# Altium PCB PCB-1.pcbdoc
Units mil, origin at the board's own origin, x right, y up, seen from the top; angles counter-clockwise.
Board outline 1312.9 x 463.6 mil, 2 copper layers (Top Layer, Bottom Layer), stack 62.2 mil thick; 18 components, 12 nets, 66 pads, 14 vias.
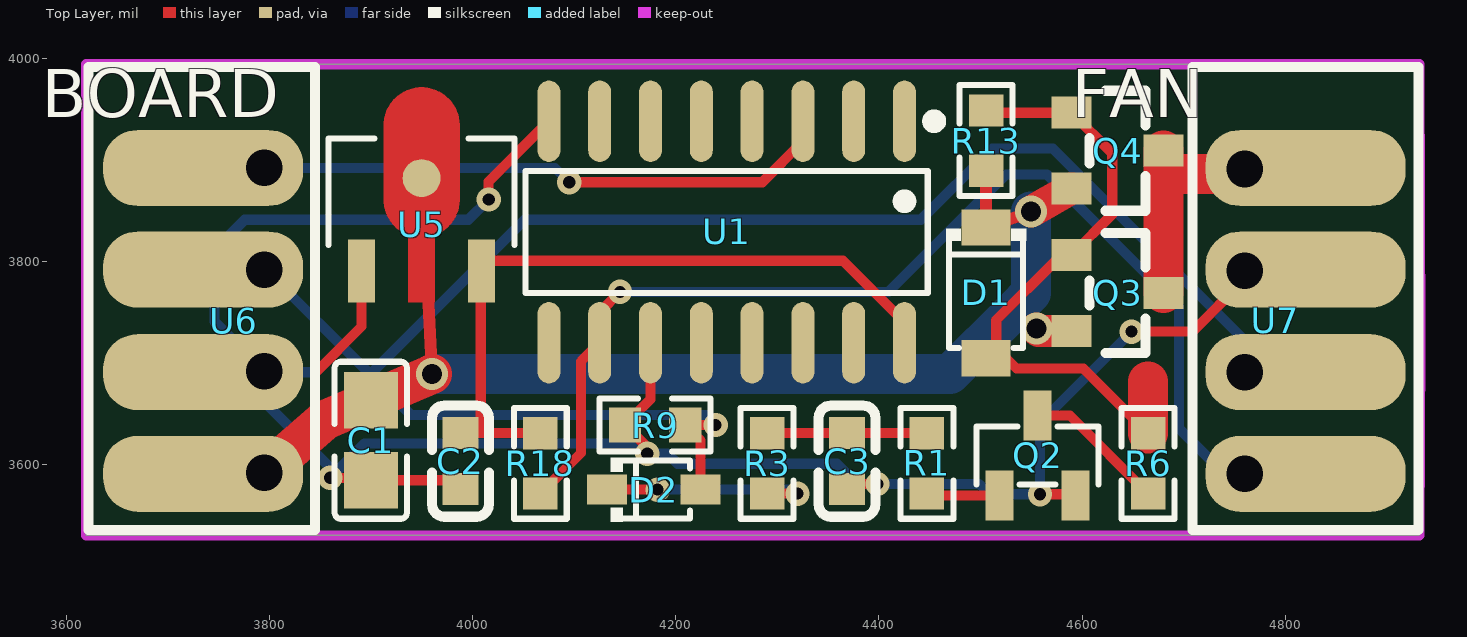
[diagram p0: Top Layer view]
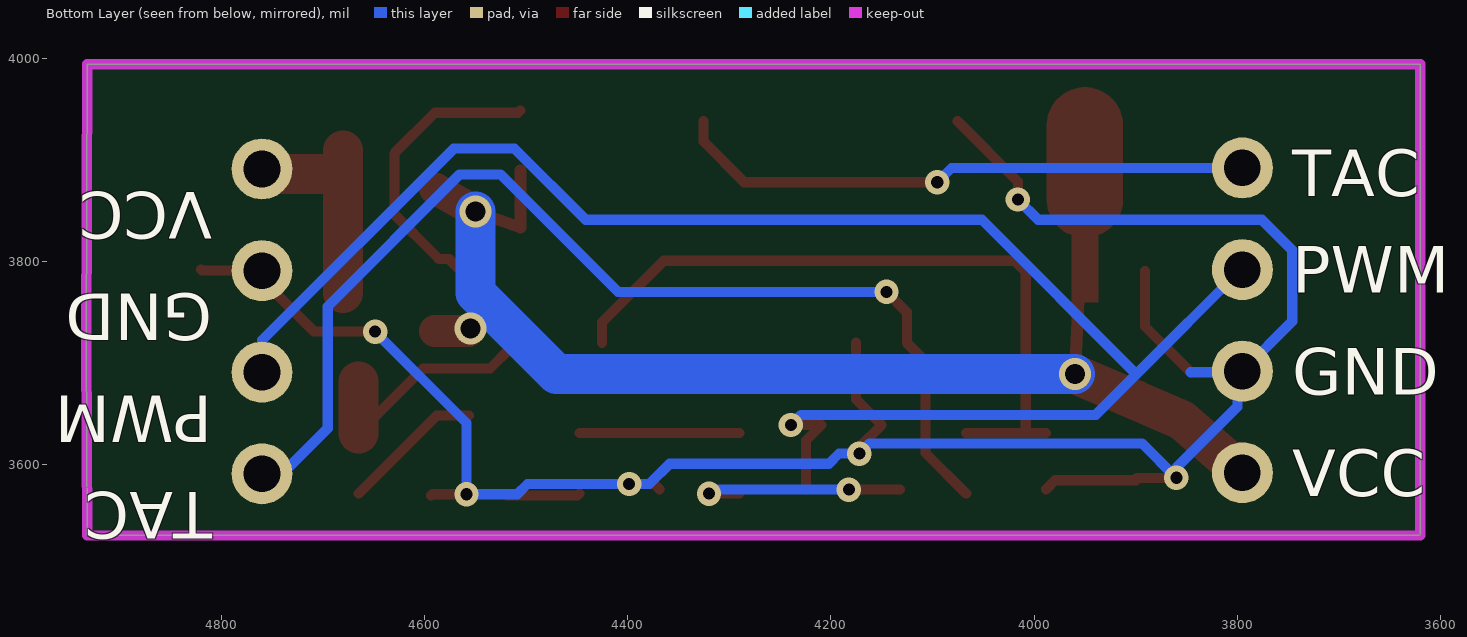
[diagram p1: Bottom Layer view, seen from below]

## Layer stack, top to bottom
Top Solder Mask Layer: solder mask 0.4, Dk 3.3
Top Layer: signal copper 1.4
Dielectric1: surface 59.4, FR4, Dk 4.5
Bottom Layer: signal copper 1.4
Bottom Solder Mask Layer: solder mask 0.4, Dk 3.3

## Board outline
3620,3993.8 4932,3993.8 4932.9,3718.8 4932,3530.2 3620,3530.2

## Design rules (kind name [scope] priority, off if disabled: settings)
BoardOutlineClearance copperThickness1oz [All] p0: genericclearance=10 ignorepadtopadclearanceinfootprint=FALSE except(0: Arc-SplitContinuation Track-SplitContinuation SMDPad-SplitContinuation THPad-SplitContinuation Via-SplitContinuation Fill-SplitContinuation Poly-SplitContinuation Region-SplitContinuation Text-SplitContinuation)
BoardOutlineClearance safeClearance2 [All] p0: genericclearance=10 ignorepadtopadclearanceinfootprint=FALSE except(0: Arc-SplitContinuation Track-SplitContinuation SMDPad-SplitContinuation THPad-SplitContinuation Via-SplitContinuation Fill-SplitContinuation Poly-SplitContinuation Region-SplitContinuation Text-SplitContinuation)
BoardOutlineClearance Plane_innerPlane [All] p0: genericclearance=10 ignorepadtopadclearanceinfootprint=FALSE except(0: Arc-SplitContinuation Track-SplitContinuation SMDPad-SplitContinuation THPad-SplitContinuation Via-SplitContinuation Fill-SplitContinuation Poly-SplitContinuation Region-SplitContinuation Text-SplitContinuation)
BoardOutlineClearance Copper_copperRegion [All] p0: genericclearance=10 ignorepadtopadclearanceinfootprint=FALSE except(0: Arc-SplitContinuation Track-SplitContinuation SMDPad-SplitContinuation THPad-SplitContinuation Via-SplitContinuation Fill-SplitContinuation Poly-SplitContinuation Region-SplitContinuation Text-SplitContinuation)
BoardOutlineClearance otherClearance [All] p0: genericclearance=10 ignorepadtopadclearanceinfootprint=FALSE except(0: Arc-SplitContinuation Track-SplitContinuation SMDPad-SplitContinuation THPad-SplitContinuation Via-SplitContinuation Fill-SplitContinuation Poly-SplitContinuation Region-SplitContinuation Text-SplitContinuation)
Clearance copperThickness1oz [All] p1: gap=7 ignorepadtopadclearanceinfootprint=FALSE
Clearance safeClearance2 [(InNet('VCC-IN') OR InNet('VCC-OUT'))] p1: gap=7 ignorepadtopadclearanceinfootprint=FALSE
Clearance Plane_innerPlane [All] p1: gap=7 ignorepadtopadclearanceinfootprint=FALSE
Clearance Copper_copperRegion [All] p1: gap=7 ignorepadtopadclearanceinfootprint=FALSE
Clearance otherClearance [All] p1: gap=7 ignorepadtopadclearanceinfootprint=FALSE
DiffPairsRouting differentialPair [All] p1: maxuncoupledlength=10 minlimit=5.9843 maxlimit=Infinity mostfreqgap=5.9843 toplayer_minwidth=5 toplayer_prefwidth=10 toplayer_maxwidth=100 bottomlayer_minwidth=5 bottomlayer_prefwidth=10 bottomlayer_maxwidth=100
PasteMaskExpansion pasteMaskExpansion [All] p1: expansion=0
PlaneConnect innerPlane [All] p1: planeconnectstyle=Relief reliefexpansion=20 reliefentries=4 reliefconductorwidth=10 reliefairgap=10
PolygonConnect copperRegion [All] p1: connectstyle=Direct reliefentries=4 reliefconductorwidth=10 polygonreliefangle="90 Angle" airgapwidth=10
RoutingVias viaSize [All] p1: viastyle="Through Hole" holewidth=12.0078 minholewidth=11.811 maxholewidth=248.0314 width=12.0078 minwidth=11.811 maxwidth=248.0314
RoutingVias viaSize2oz [All] p1: viastyle="Through Hole" holewidth=23.622 minholewidth=19.685 maxholewidth=248.0314 width=23.622 minwidth=19.685 maxwidth=248.0314
RoutingVias "no vias" [All] p1: viastyle="Through Hole" holewidth=0.3938 minholewidth=0.3938 maxholewidth=0.3938 width=0.3938 minwidth=0.3938 maxwidth=0.3938
SolderMaskExpansion solderMaskExpansion [IsVia] p1: useseparateexpansions=TRUE expansion=-1000 expansionbottom=-1000
SolderMaskExpansion solderMaskExpansion [All] p2: useseparateexpansions=TRUE expansion=2.0079 expansionbottom=2.0079
Width copperThickness1oz [All] p1: maxlimit=100 minlimit=5 preferedwidth=10
Width copperThickness2oz [All] p1: maxlimit=39 minlimit=39 preferedwidth=39

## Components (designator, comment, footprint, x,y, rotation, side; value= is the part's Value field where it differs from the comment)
C1 "10uF" C0805 3900,3623.8 r270 top
C2 "10uF" C0603 3988.2,3603.2 r270 top
C3 "47nF" C0603 4368.7,3603.2 r90 top
D1 "MMSZ5240B" SOD-123_L2.7-W1.6-LS3.7-RD 4505.6,3768.8 r270 top
D2 "1N5819WS" SOD-323_L1.8-W1.3-LS2.5-RD 4178.5,3575.2 r0 top
Q2 "SS8050(RANGE:200-350)" SOT-23-3_L2.9-W1.3-P1.90-LS2.4-BR 4556.2,3608.8 r270 top
Q3 "AO3401A" SOT-23_L2.9-W1.3-P1.90-LS2.4-BR 4635,3768.8 r180 top
Q4 "AO3401A" SOT-23_L2.9-W1.3-P1.90-LS2.4-BR 4635,3908.8 r180 top
R1 "10kΩ" R0603#1 4447.4,3601 r270 top
R3 "1kΩ" R0603#1 4290,3601 r90 top
R6 "10kΩ" R0603#1 4665,3601 r90 top
R9 "10kΩ" R0603#2 4179.7,3638.8 r0 top
R13 "20kΩ" R0603#2 4505.6,3918.8 r270 top
R18 "10kΩ" R0603#1 4066.9,3601 r90 top
U1 "CD4040BM/TR" SOP-16_L9.9-W3.9-P1.27-LS6.0-BL 4250.3,3828.8 r180 top
U5 "HT7533-1" SOT-89-3_L4.5-W2.5-P1.50-LS4.2-BR 3950,3843.8 r270 top
U6 "" "4P solder pads" 3785,3738.8 r0 top
U7 "" "4P solder pads" 4770,3743.8 r180 top

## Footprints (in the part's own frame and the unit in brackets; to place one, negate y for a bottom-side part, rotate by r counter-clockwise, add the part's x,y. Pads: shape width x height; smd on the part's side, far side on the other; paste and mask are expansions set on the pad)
"4P solder pads" [mil]
  rrect90% 196.9x74.8 smd: 1(-50,153) 2(-50,53) 3(-50,-48) 4(-50,-148)
  round 60 hole 36: 1(10,153) 2(10,53) 3(10,-47) 4(10,-147)
C0603 [mil]
  rect 31.5x35.4 smd: 1(-27.6,0) 2(27.6,0)
  silkscreen extent -55,-28 55,28
C0805 [mil]
  rect 55.5x53.1 smd paste-3937 mask+2: 1(-39.4,0) 2(39.4,0)
  silkscreen extent -77,-36 77,36
R0603#1 [mil]
  rect 31.8x34 smd paste-3937 mask+2: 1(-29.7,0) 2(29.7,0)
  silkscreen extent -55,-26 55,26
R0603#2 [mil]
  rect 31.8x34 smd paste-3937 mask+2: 1(-29.6,0) 2(29.7,0)
  silkscreen extent -54,-26 55,26
SOD-123_L2.7-W1.6-LS3.7-RD [mil]
  rect 35.8x48 smd: 1(-64.4,0) 2(64.4,0)
  silkscreen extent -63,-39 54,39
SOD-323_L1.8-W1.3-LS2.5-RD [mil]
  rect 39.4x29.5 smd: 1(-46.2,0) 2(46.1,0)
  silkscreen extent -42,-32 36,32
SOP-16_L9.9-W3.9-P1.27-LS6.0-BL [mil]
  oval 22.6x80.2 smd: 1(-175,-109) 2(-125,-109) 3(-75,-109) 4(-25,-109) 5(25,-109) 6(75,-109) 7(125,-109) 8(175,-109) 9(175,109) 10(125,109) 11(75,109) 12(25,109) 13(-25,109) 14(-75,109) 15(-125,109) 16(-175,109)
  silkscreen extent -210,-115 198,60
SOT-23-3_L2.9-W1.3-P1.90-LS2.4-BR [mil]
  rect 49.2x27.6 smd: 1(39.3,-37.4) 2(39.3,37.4) 3(-39.4,0)
  silkscreen extent -29,-60 29,60
SOT-23_L2.9-W1.3-P1.90-LS2.4-BR [mil]
  rect 39.4x31.5 smd: 1(45.3,-37.4) 2(45.3,37.4) 3(-45.3,0)
  silkscreen extent -28,-59 28,59
SOT-89-3_L4.5-W2.5-P1.50-LS4.2-BR [mil]
  rect 62x26.5 smd: 1(53.4,-59.1) 3(53.4,59.1)
  round 37.4 smd: 2(-38,0)
  Top Layer region: -89.9,37.4 -16.9,37.4 -15.1,37.4 -13.4,37.2 -11.6,37 -9.9,36.7 -8.2,36.4 -6.5,35.9 -4.8,35.4 -3.2,34.8 -1.6,34.1 0,33.4 1.6,32.5 3.1,31.6 4.5,30.7 6,29.6 7.3,28.5 8.6,27.4 9.9,26.1 11.1,24.8 12.2,23.5 13.3,22.1 14.3,20.7 15.2,19.2 16.1,17.7 16.9,16.1 17.6,13 84.4,13 84.4,-13 17.6,-13 16.9,-16.1 16.1,-17.7 15.2,-19.2 14.3,-20.7 13.3,-22.1 12.2,-23.5 11.1,-24.9 9.9,-26.1 8.6,-27.4 7.3,-28.5 6,-29.6 4.5,-30.7 3.1,-31.6 1.6,-32.5 0,-33.4 -1.6,-34.1 -3.2,-34.8 -4.8,-35.4 -6.5,-35.9 -8.2,-36.4 -9.9,-36.8 -11.6,-37 -13.4,-37.2 -15.1,-37.4 -16.9,-37.4 -89.9,-37.4 -91.6,-37.4 -93.4,-37.2 -95.1,-37 -96.8,-36.8 -98.6,-36.4 -100.3,-35.9 -101.9,-35.4 -103.6,-34.8 -105.2,-34.1 -106.8,-33.4 -108.3,-32.5 -109.8,-31.6 -111.3,-30.7 -112.7,-29.6 -114.1,-28.5 -115.4,-27.4 -116.6,-26.1 -117.8,-24.9 -119,-23.5 -120,-22.1 -121,-20.7 -122,-19.2 -122.8,-17.7 -123.6,-16.1 -124.3,-14.5 -125,-12.9 -125.6,-11.2 -126,-9.5 -126.4,-7.8 -126.8,-6.1 -127,-4.4 -127.2,-2.6 -127.3,-0.9 -127.3,0.9 -127.2,2.6 -127,4.4 -126.8,6.1 -126.4,7.8 -126,9.5 -125.6,11.2 -125,12.9 -124.3,14.5 -123.6,16.1 -122.8,17.7 -122,19.2 -121,20.7 -120,22.1 -119,23.5 -117.8,24.8 -116.6,26.1 -115.4,27.4 -114.1,28.5 -112.7,29.6 -111.3,30.7 -109.8,31.6 -108.3,32.5 -106.8,33.4 -105.2,34.1 -103.6,34.8 -101.9,35.4 -100.3,35.9 -98.6,36.4 -96.8,36.7 -95.1,37 -93.4,37.2 -91.6,37.4
  silkscreen extent -77,-92 28,92

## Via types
v1: diameter 24, hole 12, Top Layer to Bottom Layer, 11 vias
v2: diameter 31.5, hole 19.7, Top Layer to Bottom Layer, 3 vias

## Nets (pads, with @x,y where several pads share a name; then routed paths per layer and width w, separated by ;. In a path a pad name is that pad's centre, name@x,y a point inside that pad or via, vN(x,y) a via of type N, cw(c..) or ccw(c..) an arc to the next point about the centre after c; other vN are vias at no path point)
3.3V: C2.1 R18.2 U1.16 U5.3 | length 704
  Top Layer w10: C2.1 4008.2,3630.8 ; R18.2@4066.8,3630.8 4008.2,3630.8 ; U1.16 4425.3,3739.8 4364.7,3800.4 4019.1,3800.4 U5.3 4008.2,3789.6 4008.2,3630.8
$1N3: C3.2 R1.1 R3.2 | length 157.2
  Top Layer w10: R3.2@4290.1,3630.8 C3.2 R1.1@4447.3,3630.8
$1N2590: Q2.1 R1.2 | length 72.1
  Top Layer w10: R1.2 4449.3,3569.5 Q2.1
$1N6630: D2.1 R3.1 | length 219.3
  Top Layer w10: D2.1 v1(4182.3,3575.2) ; R3.1 v1(4320,3571.3)
  Bottom Layer w10: v1(4182.3,3575.2) 4316.2,3575.2 v1(4320,3571.3)
$1N7011: D1.2 Q3.1 Q4.1 R6.2 R13.1 | length 635.7
  Top Layer w10: D1.2 D1.2@4515.6,3714.4 ; R13.1 4507.9,3946.2 Q4.1 4629.7,3906.2 4629.7,3846.2 Q3.1 4585.6,3802.1 4575.6,3802.1 4515.6,3742.1 D1.2@4515.6,3714.4 ; R6.2 4601.3,3694.4 4535.6,3694.4 D1.2@4515.6,3714.4
  Top Layer w39.4: R6.2 4665.1,3681.7
$1N7284: Q2.3 R6.1 | length 140.7
  Top Layer w10: Q2.3 4588.1,3648.2 R6.1
GND: C1.2 C2.2 C3.1 Q2.2 R9.1 U1.8 U1.11 U5.1 U6.3 U7.3 | length 2293.8
  Top Layer w10: 3846,3690.8 3890.9,3735.7 U5.1 ; v1(3860,3586.8) 3898.8,3586.8 3900,3585.6 C1.2 3979.5,3584.4 C2.2 ; v1(4016,3860.8) 4016,3878.5 U1.8 ; v1(4172,3610.7) 4172,3616.9 R9.1 4175.3,3664 U1.11 ; C3.1 4373.8,3580.7 v1(4398.7,3580.7) ; v1(4558.7,3570.7) 4592.3,3570.7 Q2.2 ; v1(4648.7,3730.7) 4708.7,3730.7 4758.7,3780.7 4758.7,3789.5 4760,3790.8 4819,3790.8 U7.3@4820,3791.8
  Bottom Layer w10: 3846,3690.8 U6.3@3796,3690.8 ; v1(4016,3860.8) 3996,3840.8 3776,3840.8 3746,3810.8 3746,3740.8 3795,3691.8 U6.3@3796,3690.8 ; v1(4648.7,3730.7) 4558.7,3640.7 v1(4558.7,3570.7) 4508.7,3570.7 4498.7,3580.7 v1(4398.7,3580.7) 4378.7,3580.7 4358.7,3600.7 4202,3600.7 4192,3610.7 v1(4172,3610.7) 4162,3620.7 3893.9,3620.7 v1(3860,3586.8) 3860,3596.8 3800,3656.8 3800,3686.8 U6.3@3796,3690.8
PWM: D2.2 R9.2 U6.2 U7.2 | length 1679.7
  Top Layer w10: D2.2 4224.6,3623.5 R9.2 v1(4239.4,3638.8)
  Bottom Layer w10: U6.2@3795,3791.8 3796.4,3791.8 3899.4,3688.8 ; v1(4239.4,3638.8) 4229.4,3648.8 3939.4,3648.8 3899.4,3688.8 ; U7.2@4760,3680.8 4760,3690.8 4760,3722.2 4571.4,3910.8 4511.4,3910.8 4441.4,3840.8 4051.4,3840.8 3899.4,3688.8
TACHO: R18.1 U1.10 U7.1 | length 1086
  Top Layer w10: R18.1 4106.9,3611.3 4106.9,3701.4 U1.10 4125.3,3749.8 v1(4145.3,3769.8)
  Bottom Layer w10: v1(4145.3,3769.8) 4409.6,3769.8 4525.3,3885.5 4565.3,3885.5 4695.3,3755.5 4695.3,3635.5 4740,3590.8 U7.1@4760,3590.8
TACHOBOARD: U1.3 U6.1 | length 572.7
  Top Layer w10: v1(4095.3,3877.8) 4285.3,3877.8 4325.3,3917.8 U1.3
  Bottom Layer w10: U6.1@3795,3891.8 4081.3,3891.8 v1(4095.3,3877.8)
VCC-IN: C1.1 D1.1 Q3.2 Q4.2 R13.2 U5.2 U6.4 | length 1319.4
  Top Layer w11.8: U5.2@3950,3897.2 v2(3960,3688.8) ; R13.2 D1.1 v2(4550,3848.8)
  Top Layer w31.5: v2(4550,3848.8) Q4.2 ; v2(4555,3733.8) 4557.4,3731.4 Q3.2
  Top Layer w39.4: U6.4@3795,3591.8 3855,3643.8 C1.1 v2(3960,3688.8)
  Bottom Layer w19.7: 4532.6,3751.4 4537.4,3751.4 v2(4555,3733.8)
  Bottom Layer w39.4: v2(3960,3688.8) 4470,3688.8 4532.6,3751.4 4550,3768.8 v2(4550,3848.8)
VCC-OUT: Q3.3 Q4.3 U7.4 | length 210
  Top Layer w39.4: Q3.3 Q4.3 ; 4690,3885.8 U7.4@4760,3885.8
pads on no net: U1.1 U1.2 U1.4 U1.5 U1.6 U1.7 U1.9 U1.12 U1.13 U1.14 U1.15

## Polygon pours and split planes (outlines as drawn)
GND on Top Layer (solid, remove dead copper, pour order 0): 3000,4563.8 3000,3168.8 5585,3168.8 5585,4563.8
GND on Bottom Layer (solid, remove dead copper, pour order 2): 3047.5,4395 3047.5,3000 5632.5,3000 5632.5,4395

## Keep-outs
Board Outline Layer:
  the board outline again, w10

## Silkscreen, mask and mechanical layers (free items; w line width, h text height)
Top Silkscreen Layer:
  lines w10: 3622.3,3535.3 3622.3,3991.1 3845,3991.1 3845,3535.3 3622.3,3535.3 ; 4708.7,3535.3 4708.7,3991.1 4931.3,3991.1 4931.3,3535.3 4708.7,3535.3
  text "BOARD" at 3575.6,3941.5 h47.2
  text "FAN" at 4589.7,3941.5 h47.2

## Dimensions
3455,3993.8 to 3455,3538.8 on Document Layer
3620,3318.8 to 4930,3318.8 on Document Layer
